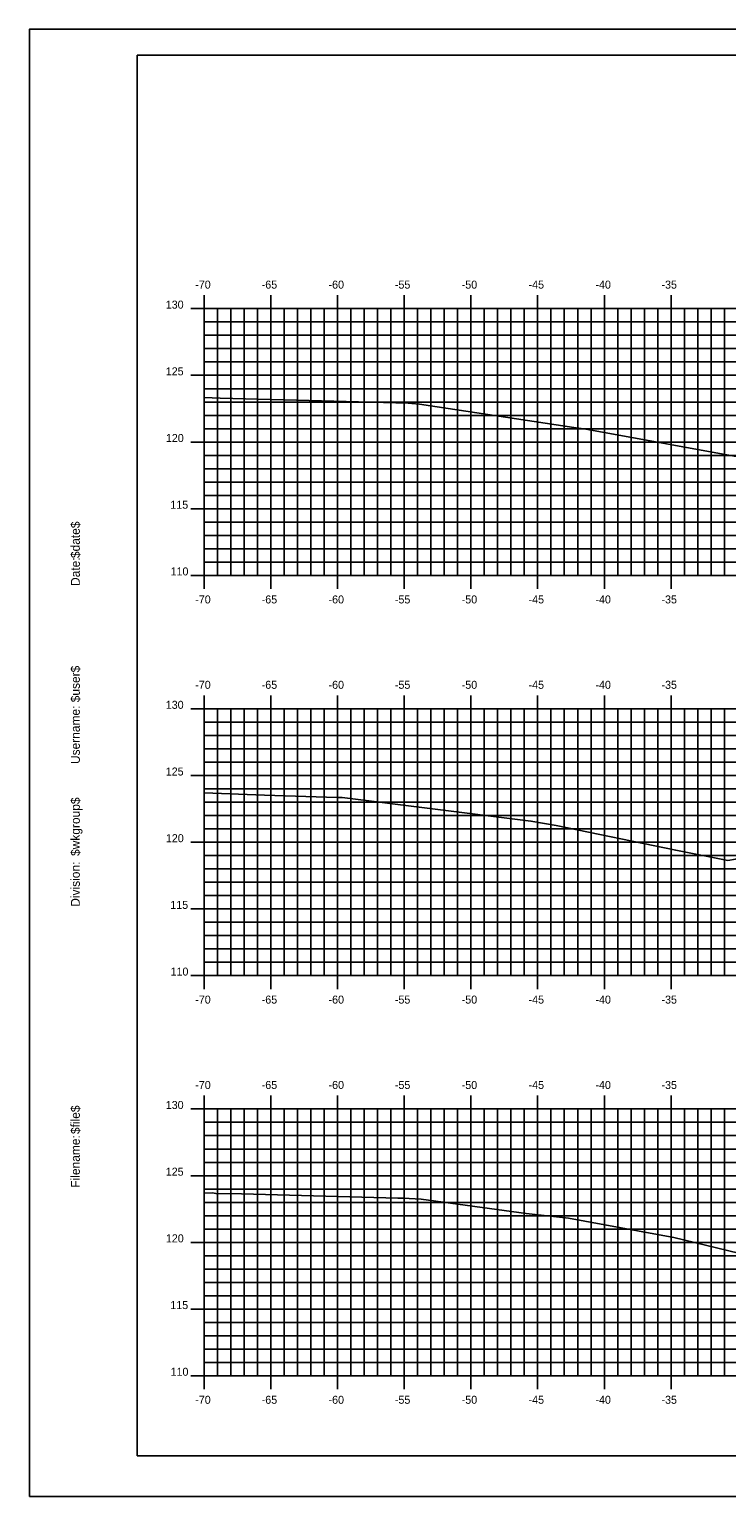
# Model space of a CAD drawing. Extents: x 852404 to 852575, y 365624 to 365734.
# Drawn here: x 852403.7 to 852456, y 365624 to 365734 of the extents above; entities that cross this region are included whole.
import ezdxf

# ---------------------------------------------------------------- set-up
doc = ezdxf.new("R2010")
doc.units = 0
for name, color, linetype in [('BORDER', 7, 'Continuous'), ('H_V ANNOTATION', 7, 'Continuous'), ('M_Roadway_Centerline', 7, 'Continuous'), ('MAJOR', 7, 'Continuous'), ('MINOR', 7, 'Continuous'), ('PLOT BOUNDARY', 7, 'Continuous'), ('S_Roadway_Centerline', 7, 'Continuous')]:
    doc.layers.add(name, color=color, linetype=linetype)

msp = doc.modelspace()

# ---------------------------------------------------------------- linework, layer by layer
at = {"layer": 'BORDER'}
msp.add_lwpolyline([(852411.79, 365627.03), (852571.79, 365627.03), (852571.79, 365732.03), (852411.79, 365732.03)], close=True, dxfattribs=at)
at = {"layer": 'MAJOR'}
for p, q in [((852416.79, 365714.03), (852416.79, 365713.03)), ((852421.79, 365714.03), (852421.79, 365713.03)), ((852426.79, 365714.03), (852426.79, 365713.03)), ((852431.79, 365714.03), (852431.79, 365713.03)), ((852436.79, 365714.03), (852436.79, 365713.03)), ((852441.79, 365714.03), (852441.79, 365713.03)), ((852446.79, 365714.03), (852446.79, 365713.03)), ((852451.79, 365714.03), (852451.79, 365713.03)), ((852415.79, 365713.03), (852416.79, 365713.03)), ((852416.79, 365713.03), (852556.79, 365713.03)), ((852416.79, 365693.03), (852416.79, 365713.03)), ((852416.79, 365693.03), (852416.79, 365713.03)), ((852416.79, 365713.03), (852556.79, 365713.03)), ((852421.79, 365693.03), (852421.79, 365713.03)), ((852426.79, 365693.03), (852426.79, 365713.03)), ((852431.79, 365693.03), (852431.79, 365713.03)), ((852436.79, 365693.03), (852436.79, 365713.03)), ((852441.79, 365693.03), (852441.79, 365713.03)), ((852446.79, 365693.03), (852446.79, 365713.03)), ((852451.79, 365693.03), (852451.79, 365713.03)), ((852415.79, 365708.03), (852416.79, 365708.03)), ((852416.79, 365708.03), (852556.79, 365708.03)), ((852415.79, 365703.03), (852416.79, 365703.03)), ((852416.79, 365703.03), (852556.79, 365703.03)), ((852415.79, 365698.03), (852416.79, 365698.03)), ((852416.79, 365698.03), (852556.79, 365698.03)), ((852415.79, 365693.03), (852416.79, 365693.03)), ((852416.79, 365693.03), (852556.79, 365693.03)), ((852416.79, 365693.03), (852556.79, 365693.03)), ((852416.79, 365692.02), (852416.79, 365693.03)), ((852421.79, 365692.02), (852421.79, 365693.03)), ((852426.79, 365692.02), (852426.79, 365693.03)), ((852431.79, 365692.02), (852431.79, 365693.03)), ((852436.79, 365692.02), (852436.79, 365693.03)), ((852441.79, 365692.02), (852441.79, 365693.03)), ((852446.79, 365692.02), (852446.79, 365693.03)), ((852451.79, 365692.02), (852451.79, 365693.03)), ((852416.79, 365684.03), (852416.79, 365683.03)), ((852421.79, 365684.03), (852421.79, 365683.03)), ((852426.79, 365684.03), (852426.79, 365683.03)), ((852431.79, 365684.03), (852431.79, 365683.03)), ((852436.79, 365684.03), (852436.79, 365683.03)), ((852441.79, 365684.03), (852441.79, 365683.03)), ((852446.79, 365684.03), (852446.79, 365683.03)), ((852451.79, 365684.03), (852451.79, 365683.03)), ((852415.79, 365683.03), (852416.79, 365683.03)), ((852416.79, 365683.03), (852556.79, 365683.03)), ((852416.79, 365663.03), (852416.79, 365683.03)), ((852416.79, 365663.03), (852416.79, 365683.03)), ((852416.79, 365683.03), (852556.79, 365683.03)), ((852421.79, 365663.03), (852421.79, 365683.03)), ((852426.79, 365663.03), (852426.79, 365683.03)), ((852431.79, 365663.03), (852431.79, 365683.03)), ((852436.79, 365663.03), (852436.79, 365683.03)), ((852441.79, 365663.03), (852441.79, 365683.03)), ((852446.79, 365663.03), (852446.79, 365683.03)), ((852451.79, 365663.03), (852451.79, 365683.03)), ((852415.79, 365678.03), (852416.79, 365678.03)), ((852416.79, 365678.03), (852556.79, 365678.03)), ((852415.79, 365673.03), (852416.79, 365673.03)), ((852416.79, 365673.03), (852556.79, 365673.03)), ((852415.79, 365668.03), (852416.79, 365668.03)), ((852416.79, 365668.03), (852556.79, 365668.03)), ((852415.79, 365663.03), (852416.79, 365663.03)), ((852416.79, 365663.03), (852556.79, 365663.03)), ((852416.79, 365663.03), (852556.79, 365663.03)), ((852416.79, 365662.02), (852416.79, 365663.03)), ((852421.79, 365662.02), (852421.79, 365663.03)), ((852426.79, 365662.02), (852426.79, 365663.03)), ((852431.79, 365662.02), (852431.79, 365663.03)), ((852436.79, 365662.02), (852436.79, 365663.03)), ((852441.79, 365662.02), (852441.79, 365663.03)), ((852446.79, 365662.02), (852446.79, 365663.03)), ((852451.79, 365662.02), (852451.79, 365663.03)), ((852416.79, 365654.03), (852416.79, 365653.03)), ((852421.79, 365654.03), (852421.79, 365653.03)), ((852426.79, 365654.03), (852426.79, 365653.03)), ((852431.79, 365654.03), (852431.79, 365653.03)), ((852436.79, 365654.03), (852436.79, 365653.03)), ((852441.79, 365654.03), (852441.79, 365653.03)), ((852446.79, 365654.03), (852446.79, 365653.03)), ((852451.79, 365654.03), (852451.79, 365653.03)), ((852415.79, 365653.03), (852416.79, 365653.03)), ((852416.79, 365653.03), (852556.79, 365653.03)), ((852416.79, 365633.03), (852416.79, 365653.03)), ((852416.79, 365633.03), (852416.79, 365653.03)), ((852416.79, 365653.03), (852556.79, 365653.03)), ((852421.79, 365633.03), (852421.79, 365653.03)), ((852426.79, 365633.03), (852426.79, 365653.03)), ((852431.79, 365633.03), (852431.79, 365653.03)), ((852436.79, 365633.03), (852436.79, 365653.03)), ((852441.79, 365633.03), (852441.79, 365653.03)), ((852446.79, 365633.03), (852446.79, 365653.03)), ((852451.79, 365633.03), (852451.79, 365653.03)), ((852415.79, 365648.03), (852416.79, 365648.03)), ((852416.79, 365648.03), (852556.79, 365648.03)), ((852415.79, 365643.03), (852416.79, 365643.03)), ((852416.79, 365643.03), (852556.79, 365643.03)), ((852415.79, 365638.03), (852416.79, 365638.03)), ((852416.79, 365638.03), (852556.79, 365638.03)), ((852415.79, 365633.03), (852416.79, 365633.03)), ((852416.79, 365633.03), (852556.79, 365633.03)), ((852416.79, 365633.03), (852556.79, 365633.03)), ((852416.79, 365632.02), (852416.79, 365633.03)), ((852421.79, 365632.02), (852421.79, 365633.03)), ((852426.79, 365632.02), (852426.79, 365633.03)), ((852431.79, 365632.02), (852431.79, 365633.03)), ((852436.79, 365632.02), (852436.79, 365633.03)), ((852441.79, 365632.02), (852441.79, 365633.03)), ((852446.79, 365632.02), (852446.79, 365633.03)), ((852451.79, 365632.02), (852451.79, 365633.03))]:
    msp.add_line(p, q, dxfattribs=at)
at = {"layer": 'MINOR'}
for p, q in [((852417.79, 365693.03), (852417.79, 365713.03)), ((852418.79, 365693.03), (852418.79, 365713.03)), ((852419.79, 365693.03), (852419.79, 365713.03)), ((852420.79, 365693.03), (852420.79, 365713.03)), ((852422.79, 365693.03), (852422.79, 365713.03)), ((852423.79, 365693.03), (852423.79, 365713.03)), ((852424.79, 365693.03), (852424.79, 365713.03)), ((852425.79, 365693.03), (852425.79, 365713.03)), ((852427.79, 365693.03), (852427.79, 365713.03)), ((852428.79, 365693.03), (852428.79, 365713.03)), ((852429.79, 365693.03), (852429.79, 365713.03)), ((852430.79, 365693.03), (852430.79, 365713.03)), ((852432.79, 365693.03), (852432.79, 365713.03)), ((852433.79, 365693.03), (852433.79, 365713.03)), ((852434.79, 365693.03), (852434.79, 365713.03)), ((852435.79, 365693.03), (852435.79, 365713.03)), ((852437.79, 365693.03), (852437.79, 365713.03)), ((852438.79, 365693.03), (852438.79, 365713.03)), ((852439.79, 365693.03), (852439.79, 365713.03)), ((852440.79, 365693.03), (852440.79, 365713.03)), ((852442.79, 365693.03), (852442.79, 365713.03)), ((852443.79, 365693.03), (852443.79, 365713.03)), ((852444.79, 365693.03), (852444.79, 365713.03)), ((852445.79, 365693.03), (852445.79, 365713.03)), ((852447.79, 365693.03), (852447.79, 365713.03)), ((852448.79, 365693.03), (852448.79, 365713.03)), ((852449.79, 365693.03), (852449.79, 365713.03)), ((852450.79, 365693.03), (852450.79, 365713.03)), ((852452.79, 365693.03), (852452.79, 365713.03)), ((852453.79, 365693.03), (852453.79, 365713.03)), ((852454.79, 365693.03), (852454.79, 365713.03)), ((852455.79, 365693.03), (852455.79, 365713.03)), ((852416.79, 365712.03), (852556.79, 365712.03)), ((852416.79, 365712.03), (852417.79, 365712.03)), ((852416.79, 365711.03), (852556.79, 365711.03)), ((852416.79, 365711.03), (852417.79, 365711.03)), ((852416.79, 365710.03), (852556.79, 365710.03)), ((852416.79, 365710.03), (852417.79, 365710.03)), ((852416.79, 365709.03), (852556.79, 365709.03)), ((852416.79, 365709.03), (852417.79, 365709.03)), ((852416.79, 365707.03), (852556.79, 365707.03)), ((852416.79, 365707.03), (852417.79, 365707.03)), ((852416.79, 365706.03), (852556.79, 365706.03)), ((852416.79, 365706.03), (852417.79, 365706.03)), ((852416.79, 365705.03), (852556.79, 365705.03)), ((852416.79, 365705.03), (852417.79, 365705.03)), ((852416.79, 365704.03), (852556.79, 365704.03)), ((852416.79, 365704.03), (852417.79, 365704.03)), ((852416.79, 365702.03), (852556.79, 365702.03)), ((852416.79, 365702.03), (852417.79, 365702.03)), ((852416.79, 365701.03), (852556.79, 365701.03)), ((852416.79, 365701.03), (852417.79, 365701.03)), ((852416.79, 365700.03), (852556.79, 365700.03)), ((852416.79, 365700.03), (852417.79, 365700.03)), ((852416.79, 365699.03), (852556.79, 365699.03)), ((852416.79, 365699.03), (852417.79, 365699.03)), ((852416.79, 365697.03), (852556.79, 365697.03)), ((852416.79, 365697.03), (852417.79, 365697.03)), ((852416.79, 365696.03), (852556.79, 365696.03)), ((852416.79, 365696.03), (852417.79, 365696.03)), ((852416.79, 365695.03), (852556.79, 365695.03)), ((852416.79, 365695.03), (852417.79, 365695.03)), ((852416.79, 365694.03), (852556.79, 365694.03)), ((852416.79, 365694.03), (852417.79, 365694.03)), ((852417.79, 365663.03), (852417.79, 365683.03)), ((852418.79, 365663.03), (852418.79, 365683.03)), ((852419.79, 365663.03), (852419.79, 365683.03)), ((852420.79, 365663.03), (852420.79, 365683.03)), ((852422.79, 365663.03), (852422.79, 365683.03)), ((852423.79, 365663.03), (852423.79, 365683.03)), ((852424.79, 365663.03), (852424.79, 365683.03)), ((852425.79, 365663.03), (852425.79, 365683.03)), ((852427.79, 365663.03), (852427.79, 365683.03)), ((852428.79, 365663.03), (852428.79, 365683.03)), ((852429.79, 365663.03), (852429.79, 365683.03)), ((852430.79, 365663.03), (852430.79, 365683.03)), ((852432.79, 365663.03), (852432.79, 365683.03)), ((852433.79, 365663.03), (852433.79, 365683.03)), ((852434.79, 365663.03), (852434.79, 365683.03)), ((852435.79, 365663.03), (852435.79, 365683.03)), ((852437.79, 365663.03), (852437.79, 365683.03)), ((852438.79, 365663.03), (852438.79, 365683.03)), ((852439.79, 365663.03), (852439.79, 365683.03)), ((852440.79, 365663.03), (852440.79, 365683.03)), ((852442.79, 365663.03), (852442.79, 365683.03)), ((852443.79, 365663.03), (852443.79, 365683.03)), ((852444.79, 365663.03), (852444.79, 365683.03)), ((852445.79, 365663.03), (852445.79, 365683.03)), ((852447.79, 365663.03), (852447.79, 365683.03)), ((852448.79, 365663.03), (852448.79, 365683.03)), ((852449.79, 365663.03), (852449.79, 365683.03)), ((852450.79, 365663.03), (852450.79, 365683.03)), ((852452.79, 365663.03), (852452.79, 365683.03)), ((852453.79, 365663.03), (852453.79, 365683.03)), ((852454.79, 365663.03), (852454.79, 365683.03)), ((852455.79, 365663.03), (852455.79, 365683.03)), ((852416.79, 365682.03), (852556.79, 365682.03)), ((852416.79, 365682.03), (852417.79, 365682.03)), ((852416.79, 365681.03), (852556.79, 365681.03)), ((852416.79, 365681.03), (852417.79, 365681.03)), ((852416.79, 365680.03), (852556.79, 365680.03)), ((852416.79, 365680.03), (852417.79, 365680.03)), ((852416.79, 365679.03), (852556.79, 365679.03)), ((852416.79, 365679.03), (852417.79, 365679.03)), ((852416.79, 365677.03), (852556.79, 365677.03)), ((852416.79, 365677.03), (852417.79, 365677.03)), ((852416.79, 365676.03), (852556.79, 365676.03)), ((852416.79, 365676.03), (852417.79, 365676.03)), ((852416.79, 365675.03), (852556.79, 365675.03)), ((852416.79, 365675.03), (852417.79, 365675.03)), ((852416.79, 365674.03), (852556.79, 365674.03)), ((852416.79, 365674.03), (852417.79, 365674.03)), ((852416.79, 365672.03), (852556.79, 365672.03)), ((852416.79, 365672.03), (852417.79, 365672.03)), ((852416.79, 365671.03), (852556.79, 365671.03)), ((852416.79, 365671.03), (852417.79, 365671.03)), ((852416.79, 365670.03), (852556.79, 365670.03)), ((852416.79, 365670.03), (852417.79, 365670.03)), ((852416.79, 365669.03), (852556.79, 365669.03)), ((852416.79, 365669.03), (852417.79, 365669.03)), ((852416.79, 365667.03), (852556.79, 365667.03)), ((852416.79, 365667.03), (852417.79, 365667.03)), ((852416.79, 365666.03), (852556.79, 365666.03)), ((852416.79, 365666.03), (852417.79, 365666.03)), ((852416.79, 365665.03), (852556.79, 365665.03)), ((852416.79, 365665.03), (852417.79, 365665.03)), ((852416.79, 365664.03), (852556.79, 365664.03)), ((852416.79, 365664.03), (852417.79, 365664.03)), ((852417.79, 365633.03), (852417.79, 365653.03)), ((852418.79, 365633.03), (852418.79, 365653.03)), ((852419.79, 365633.03), (852419.79, 365653.03)), ((852420.79, 365633.03), (852420.79, 365653.03)), ((852422.79, 365633.03), (852422.79, 365653.03)), ((852423.79, 365633.03), (852423.79, 365653.03)), ((852424.79, 365633.03), (852424.79, 365653.03)), ((852425.79, 365633.03), (852425.79, 365653.03)), ((852427.79, 365633.03), (852427.79, 365653.03)), ((852428.79, 365633.03), (852428.79, 365653.03)), ((852429.79, 365633.03), (852429.79, 365653.03)), ((852430.79, 365633.03), (852430.79, 365653.03)), ((852432.79, 365633.03), (852432.79, 365653.03)), ((852433.79, 365633.03), (852433.79, 365653.03)), ((852434.79, 365633.03), (852434.79, 365653.03)), ((852435.79, 365633.03), (852435.79, 365653.03)), ((852437.79, 365633.03), (852437.79, 365653.03)), ((852438.79, 365633.03), (852438.79, 365653.03)), ((852439.79, 365633.03), (852439.79, 365653.03)), ((852440.79, 365633.03), (852440.79, 365653.03)), ((852442.79, 365633.03), (852442.79, 365653.03)), ((852443.79, 365633.03), (852443.79, 365653.03)), ((852444.79, 365633.03), (852444.79, 365653.03)), ((852445.79, 365633.03), (852445.79, 365653.03)), ((852447.79, 365633.03), (852447.79, 365653.03)), ((852448.79, 365633.03), (852448.79, 365653.03)), ((852449.79, 365633.03), (852449.79, 365653.03)), ((852450.79, 365633.03), (852450.79, 365653.03)), ((852452.79, 365633.03), (852452.79, 365653.03)), ((852453.79, 365633.03), (852453.79, 365653.03)), ((852454.79, 365633.03), (852454.79, 365653.03)), ((852455.79, 365633.03), (852455.79, 365653.03)), ((852416.79, 365652.03), (852556.79, 365652.03)), ((852416.79, 365652.03), (852417.79, 365652.03)), ((852416.79, 365651.03), (852556.79, 365651.03)), ((852416.79, 365651.03), (852417.79, 365651.03)), ((852416.79, 365650.03), (852556.79, 365650.03)), ((852416.79, 365650.03), (852417.79, 365650.03)), ((852416.79, 365649.03), (852556.79, 365649.03)), ((852416.79, 365649.03), (852417.79, 365649.03)), ((852416.79, 365647.03), (852556.79, 365647.03)), ((852416.79, 365647.03), (852417.79, 365647.03)), ((852416.79, 365646.03), (852556.79, 365646.03)), ((852416.79, 365646.03), (852417.79, 365646.03)), ((852416.79, 365645.03), (852556.79, 365645.03)), ((852416.79, 365645.03), (852417.79, 365645.03)), ((852416.79, 365644.03), (852556.79, 365644.03)), ((852416.79, 365644.03), (852417.79, 365644.03)), ((852416.79, 365642.03), (852556.79, 365642.03)), ((852416.79, 365642.03), (852417.79, 365642.03)), ((852416.79, 365641.03), (852556.79, 365641.03)), ((852416.79, 365641.03), (852417.79, 365641.03)), ((852416.79, 365640.03), (852556.79, 365640.03)), ((852416.79, 365640.03), (852417.79, 365640.03)), ((852416.79, 365639.03), (852556.79, 365639.03)), ((852416.79, 365639.03), (852417.79, 365639.03)), ((852416.79, 365637.03), (852556.79, 365637.03)), ((852416.79, 365637.03), (852417.79, 365637.03)), ((852416.79, 365636.03), (852556.79, 365636.03)), ((852416.79, 365636.03), (852417.79, 365636.03)), ((852416.79, 365635.03), (852556.79, 365635.03)), ((852416.79, 365635.03), (852417.79, 365635.03)), ((852416.79, 365634.03), (852556.79, 365634.03)), ((852416.79, 365634.03), (852417.79, 365634.03))]:
    msp.add_line(p, q, dxfattribs=at)
at = {"layer": 'PLOT BOUNDARY'}
msp.add_lwpolyline([(852403.7, 365623.97), (852573.7, 365623.97), (852573.7, 365733.97), (852403.7, 365733.97)], close=True, dxfattribs=at)
at = {"layer": 'S_Roadway_Centerline'}
for points in [[(852416.79, 365706.36), (852418.01, 365706.33), (852424.67, 365706.14), (852432.08, 365705.94), (852432.36, 365705.93), (852432.93, 365705.87), (852444.49, 365704.13), (852445.25, 365704.02), (852445.54, 365703.97), (852457.61, 365701.77), (852457.78, 365701.76), (852464.4, 365702.44), (852467.76, 365702.82), (852474.44, 365703.54), (852479.39, 365704.09), (852482.82, 365704.41), (852498.23, 365705.67), (852500.98, 365705.86), (852502.71, 365705.91), (852504.27, 365705.94), (852514.45, 365706.18), (852517.27, 365706.27)], [(852416.79, 365676.72), (852421.31, 365676.56), (852426.73, 365676.39), (852427.14, 365676.37), (852440.88, 365674.65), (852441.29, 365674.61), (852443.18, 365674.28), (852452.14, 365672.43), (852456.05, 365671.66), (852456.61, 365671.76), (852472.27, 365673.89), (852477.65, 365674.45), (852485.85, 365675.05), (852495.61, 365675.83), (852499.01, 365676.08), (852499.53, 365676.07), (852500.53, 365676.05), (852504.96, 365676.12), (852512.09, 365676.31), (852519.42, 365676.38)], [(852416.79, 365646.72), (852417.42, 365646.74), (852417.67, 365646.7), (852419.59, 365646.66), (852431.32, 365646.35), (852431.7, 365646.34), (852433.06, 365646.27), (852440.93, 365645.2), (852444.1, 365644.85), (852451.99, 365643.39), (852458.48, 365641.83), (852459.26, 365641.69), (852460.3, 365641.83), (852470.15, 365643.45), (852487.04, 365645.39), (852489.29, 365645.66), (852490.16, 365645.73), (852498.16, 365646.18), (852501.84, 365646.33), (852509.52, 365646.51), (852514.95, 365646.57), (852516.29, 365646.57)]]:
    msp.add_lwpolyline(points, dxfattribs=at)

# ---------------------------------------------------------------- texts
at = {"layer": 'BORDER'}
for s, p in [('$date$', (852407.48, 365694.33)), ('Date:', (852407.48, 365692.24)), ('$user$', (852407.48, 365683.52)), ('Username:', (852407.48, 365678.89)), ('$wkgroup$', (852407.48, 365672)), ('Division:', (852407.48, 365668.19)), ('$file$', (852407.48, 365651.15)), ('Filename:', (852407.48, 365647.13))]:
    msp.add_text(s, height=0.67, rotation=90, dxfattribs=at).set_placement(p)
at = {"layer": 'H_V ANNOTATION'}
for s, p in [('-70', (852416.13, 365714.53)), ('-65', (852421.11, 365714.53)), ('-60', (852426.12, 365714.53)), ('-55', (852431.09, 365714.53)), ('-50', (852436.1, 365714.53)), ('-45', (852441.11, 365714.53)), ('-40', (852446.12, 365714.53)), ('-35', (852451.07, 365714.53)), ('130', (852413.92, 365713.03)), ('125', (852413.92, 365708.03)), ('120', (852413.93, 365703.03)), ('115', (852414.26, 365698.03)), ('110', (852414.28, 365693.03)), ('-70', (852416.13, 365690.93)), ('-65', (852421.11, 365690.93)), ('-60', (852426.12, 365690.93)), ('-55', (852431.09, 365690.93)), ('-50', (852436.1, 365690.93)), ('-45', (852441.11, 365690.93)), ('-40', (852446.12, 365690.93)), ('-35', (852451.07, 365690.93)), ('-70', (852416.13, 365684.53)), ('-65', (852421.11, 365684.53)), ('-60', (852426.12, 365684.53)), ('-55', (852431.09, 365684.53)), ('-50', (852436.1, 365684.53)), ('-45', (852441.11, 365684.53)), ('-40', (852446.12, 365684.53)), ('-35', (852451.07, 365684.53)), ('130', (852413.92, 365683.03)), ('125', (852413.92, 365678.03)), ('120', (852413.93, 365673.03)), ('115', (852414.26, 365668.03)), ('110', (852414.28, 365663.03)), ('-70', (852416.13, 365660.93)), ('-65', (852421.11, 365660.93)), ('-60', (852426.12, 365660.93)), ('-55', (852431.09, 365660.93)), ('-50', (852436.1, 365660.93)), ('-45', (852441.11, 365660.93)), ('-40', (852446.12, 365660.93)), ('-35', (852451.07, 365660.93)), ('-70', (852416.13, 365654.53)), ('-65', (852421.11, 365654.53)), ('-60', (852426.12, 365654.53)), ('-55', (852431.09, 365654.53)), ('-50', (852436.1, 365654.53)), ('-45', (852441.11, 365654.53)), ('-40', (852446.12, 365654.53)), ('-35', (852451.07, 365654.53)), ('130', (852413.92, 365653.03)), ('125', (852413.92, 365648.03)), ('120', (852413.93, 365643.03)), ('115', (852414.26, 365638.03)), ('110', (852414.28, 365633.03)), ('-70', (852416.13, 365630.93)), ('-65', (852421.11, 365630.93)), ('-60', (852426.12, 365630.93)), ('-55', (852431.09, 365630.93)), ('-50', (852436.1, 365630.93)), ('-45', (852441.11, 365630.93)), ('-40', (852446.12, 365630.93)), ('-35', (852451.07, 365630.93))]:
    msp.add_text(s, height=0.6, dxfattribs=at).set_placement(p)
at = {"layer": 'M_Roadway_Centerline'}
for s, p in [('C', (852417.42, 365646.74)), ('L', (852417.42, 365646.73))]:
    msp.add_text(s, height=0.0146, dxfattribs=at).set_placement(p)
at = {"layer": 'MAJOR'}
for p in [(852416.79, 365693.03), (852416.79, 365663.03), (852416.79, 365633.03)]:
    msp.add_text('-', height=0.006, dxfattribs=at).set_placement(p)

doc.saveas('drawing.dxf')
